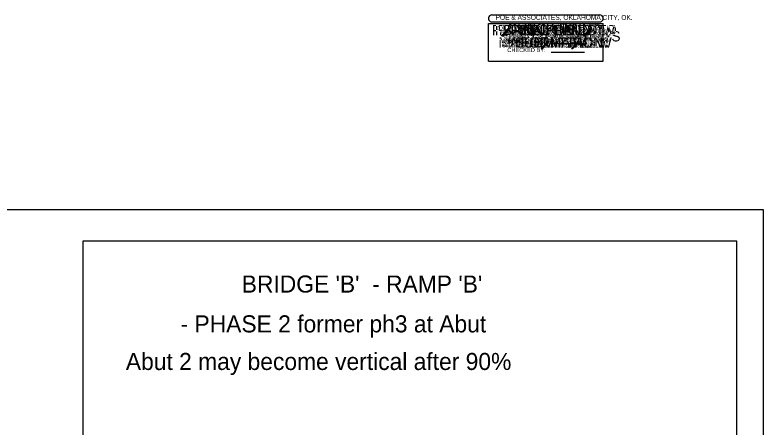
# Model space of a CAD drawing. Extents: x 570 to 2152770, y 726 to 139926.
# Drawn here: x 2152280 to 2152718.5, y 139685 to 139926.4 of the extents above; entities that cross this region are included whole.
import ezdxf

# ---------------------------------------------------------------- set-up
doc = ezdxf.new("R2010")
doc.units = 0
for name, color, linetype in [('S', 7, 'Continuous'), ('SHT_Stamp_30_Submit', 7, 'Continuous'), ('SHT_Stamp_70_Submit', 7, 'Continuous'), ('SHT_Stamp_Check_Print', 7, 'Continuous'), ('SHT_Stamp_Est_Inf', 7, 'Continuous'), ('SHT_Stamp_FFR', 7, 'Continuous'), ('SHT_Stamp_Info_Material', 7, 'Continuous'), ('SHT_Stamp_No_Const', 7, 'Continuous'), ('SHT_Stamp_No_Design', 7, 'Continuous'), ('SHT_Stamp_Plan_Hand', 7, 'Continuous'), ('SHT_Stamp_Pre_Plan', 7, 'Continuous'), ('SHT_Stamp_Prop_RW', 7, 'Continuous'), ('SHT_Stamp_Ret_Sub', 7, 'Continuous'), ('SHT_Stamp_Rev_Prop_RW', 7, 'Continuous'), ('SHT_Stamp_Rev_Sheet', 7, 'Continuous'), ('SHT_Stamp_RW_Utilities_Meeting', 7, 'Continuous'), ('SHT_Stamp_RW_Utilities_Review', 7, 'Continuous'), ('SHT_Stamp_Send_Comments', 7, 'Continuous')]:
    doc.layers.add(name, color=color, linetype=linetype)

msp = doc.modelspace()

# ---------------------------------------------------------------- linework, layer by layer
at = {"layer": 'S'}
for points in [[(2151790.38, 139812.49), (2152718.5, 139812.49), (2152718.5, 139247.24), (2151790.38, 139247.24)], [(2152319.83, 139266.32), (2152703.21, 139266.32), (2152703.21, 139793.9), (2152319.83, 139793.9)]]:
    msp.add_lwpolyline(points, close=True, dxfattribs=at)
at = {"layer": 'SHT_Stamp_30_Submit'}
for p, q in [((2152559.53, 139926.42), (2152622.84, 139926.42)), ((2152557.53, 139921.42), (2152624.84, 139921.42)), ((2152557.53, 139899.43), (2152557.53, 139921.42)), ((2152559.53, 139922.42), (2152622.84, 139922.42)), ((2152624.84, 139899.43), (2152624.84, 139921.42)), ((2152582.39, 139914.65), (2152585.5, 139918.1)), ((2152582.75, 139914.65), (2152585.86, 139918.1)), ((2152582.85, 139914.65), (2152585.96, 139918.1)), ((2152583, 139914.65), (2152586.11, 139918.1)), ((2152585.5, 139918.1), (2152586.11, 139918.1)), ((2152582.39, 139914.65), (2152583, 139914.65)), ((2152557.53, 139899.43), (2152624.84, 139899.43))]:
    msp.add_line(p, q, dxfattribs=at)
for centre, start, end in [((2152559.53, 139924.42), 89.9952, 270), ((2152622.85, 139924.42), 270, 90.0048)]:
    msp.add_arc(centre, 2, start, end, dxfattribs=at)
at = {"layer": 'SHT_Stamp_70_Submit'}
for p, q in [((2152559.53, 139926.42), (2152622.84, 139926.42)), ((2152557.53, 139921.42), (2152624.84, 139921.42)), ((2152557.53, 139899.43), (2152557.53, 139921.42)), ((2152559.53, 139922.42), (2152622.84, 139922.42)), ((2152624.84, 139899.43), (2152624.84, 139921.42)), ((2152582.39, 139914.65), (2152585.5, 139918.1)), ((2152582.75, 139914.65), (2152585.86, 139918.1)), ((2152582.85, 139914.65), (2152585.96, 139918.1)), ((2152583, 139914.65), (2152586.11, 139918.1)), ((2152585.5, 139918.1), (2152586.11, 139918.1)), ((2152582.39, 139914.65), (2152583, 139914.65)), ((2152557.53, 139899.43), (2152624.84, 139899.43))]:
    msp.add_line(p, q, dxfattribs=at)
for centre, start, end in [((2152559.53, 139924.42), 89.9952, 270), ((2152622.85, 139924.42), 270, 90.0048)]:
    msp.add_arc(centre, 2, start, end, dxfattribs=at)
at = {"layer": 'SHT_Stamp_Check_Print'}
for p, q in [((2152559.53, 139926.42), (2152622.84, 139926.42)), ((2152557.53, 139921.42), (2152624.84, 139921.42)), ((2152557.53, 139899.43), (2152557.53, 139921.42)), ((2152559.53, 139922.42), (2152622.84, 139922.42)), ((2152624.84, 139899.43), (2152624.84, 139921.42)), ((2152594.36, 139909.79), (2152613.77, 139909.79)), ((2152594.36, 139904.68), (2152613.77, 139904.68)), ((2152557.53, 139899.43), (2152624.84, 139899.43))]:
    msp.add_line(p, q, dxfattribs=at)
for centre, start, end in [((2152559.53, 139924.42), 89.9952, 270), ((2152622.85, 139924.42), 270, 90.0048)]:
    msp.add_arc(centre, 2, start, end, dxfattribs=at)
at = {"layer": 'SHT_Stamp_Est_Inf'}
for p, q in [((2152559.53, 139926.42), (2152622.84, 139926.42)), ((2152557.53, 139921.42), (2152624.84, 139921.42)), ((2152557.53, 139899.43), (2152557.53, 139921.42)), ((2152559.53, 139922.42), (2152622.84, 139922.42)), ((2152624.84, 139899.43), (2152624.84, 139921.42)), ((2152557.53, 139899.43), (2152624.84, 139899.43))]:
    msp.add_line(p, q, dxfattribs=at)
for centre, start, end in [((2152559.53, 139924.42), 89.9952, 270), ((2152622.85, 139924.42), 270, 90.0048)]:
    msp.add_arc(centre, 2, start, end, dxfattribs=at)
at = {"layer": 'SHT_Stamp_FFR'}
for p, q in [((2152559.53, 139926.42), (2152622.84, 139926.42)), ((2152557.53, 139921.42), (2152624.84, 139921.42)), ((2152557.53, 139899.43), (2152557.53, 139921.42)), ((2152559.53, 139922.42), (2152622.84, 139922.42)), ((2152624.84, 139899.43), (2152624.84, 139921.42)), ((2152557.53, 139899.43), (2152624.84, 139899.43))]:
    msp.add_line(p, q, dxfattribs=at)
for centre, start, end in [((2152559.53, 139924.42), 89.9952, 270), ((2152622.85, 139924.42), 270, 90.0048)]:
    msp.add_arc(centre, 2, start, end, dxfattribs=at)
at = {"layer": 'SHT_Stamp_Info_Material'}
for p, q in [((2152559.53, 139926.42), (2152622.84, 139926.42)), ((2152557.53, 139921.42), (2152624.84, 139921.42)), ((2152557.53, 139899.43), (2152557.53, 139921.42)), ((2152559.53, 139922.42), (2152622.84, 139922.42)), ((2152624.84, 139899.43), (2152624.84, 139921.42)), ((2152557.53, 139899.43), (2152624.84, 139899.43))]:
    msp.add_line(p, q, dxfattribs=at)
for centre, start, end in [((2152559.53, 139924.42), 89.9952, 270), ((2152622.85, 139924.42), 270, 90.0048)]:
    msp.add_arc(centre, 2, start, end, dxfattribs=at)
at = {"layer": 'SHT_Stamp_No_Const'}
for p, q in [((2152559.53, 139926.42), (2152622.84, 139926.42)), ((2152557.53, 139921.42), (2152624.84, 139921.42)), ((2152557.53, 139899.43), (2152557.53, 139921.42)), ((2152559.53, 139922.42), (2152622.84, 139922.42)), ((2152624.84, 139899.43), (2152624.84, 139921.42)), ((2152557.53, 139899.43), (2152624.84, 139899.43))]:
    msp.add_line(p, q, dxfattribs=at)
for centre, start, end in [((2152559.53, 139924.42), 89.9952, 270), ((2152622.85, 139924.42), 270, 90.0048)]:
    msp.add_arc(centre, 2, start, end, dxfattribs=at)
at = {"layer": 'SHT_Stamp_No_Design'}
for p, q in [((2152559.53, 139926.42), (2152622.84, 139926.42)), ((2152557.53, 139921.42), (2152624.84, 139921.42)), ((2152557.53, 139899.43), (2152557.53, 139921.42)), ((2152559.53, 139922.42), (2152622.84, 139922.42)), ((2152624.84, 139899.43), (2152624.84, 139921.42)), ((2152557.53, 139899.43), (2152624.84, 139899.43))]:
    msp.add_line(p, q, dxfattribs=at)
for centre, start, end in [((2152559.53, 139924.42), 89.9952, 270), ((2152622.85, 139924.42), 270, 90.0048)]:
    msp.add_arc(centre, 2, start, end, dxfattribs=at)
at = {"layer": 'SHT_Stamp_Plan_Hand'}
for p, q in [((2152559.53, 139926.42), (2152622.84, 139926.42)), ((2152557.53, 139921.42), (2152624.84, 139921.42)), ((2152557.53, 139899.43), (2152557.53, 139921.42)), ((2152559.53, 139922.42), (2152622.84, 139922.42)), ((2152624.84, 139899.43), (2152624.84, 139921.42)), ((2152557.53, 139899.43), (2152624.84, 139899.43))]:
    msp.add_line(p, q, dxfattribs=at)
for centre, start, end in [((2152559.53, 139924.42), 89.9952, 270), ((2152622.85, 139924.42), 270, 90.0048)]:
    msp.add_arc(centre, 2, start, end, dxfattribs=at)
at = {"layer": 'SHT_Stamp_Pre_Plan'}
for p, q in [((2152559.53, 139926.42), (2152622.84, 139926.42)), ((2152557.53, 139921.42), (2152624.84, 139921.42)), ((2152557.53, 139899.43), (2152557.53, 139921.42)), ((2152559.53, 139922.42), (2152622.84, 139922.42)), ((2152624.84, 139899.43), (2152624.84, 139921.42)), ((2152557.53, 139899.43), (2152624.84, 139899.43))]:
    msp.add_line(p, q, dxfattribs=at)
for centre, start, end in [((2152559.53, 139924.42), 89.9952, 270), ((2152622.85, 139924.42), 270, 90.0048)]:
    msp.add_arc(centre, 2, start, end, dxfattribs=at)
at = {"layer": 'SHT_Stamp_Prop_RW'}
for p, q in [((2152559.53, 139926.42), (2152622.84, 139926.42)), ((2152557.53, 139921.42), (2152624.84, 139921.42)), ((2152557.53, 139899.43), (2152557.53, 139921.42)), ((2152559.53, 139922.42), (2152622.84, 139922.42)), ((2152624.84, 139899.43), (2152624.84, 139921.42)), ((2152588.46, 139906.87), (2152592.3, 139911.13)), ((2152588.9, 139906.87), (2152592.74, 139911.13)), ((2152589.02, 139906.87), (2152592.86, 139911.13)), ((2152589.22, 139906.87), (2152593.06, 139911.13)), ((2152592.3, 139911.13), (2152593.06, 139911.13)), ((2152588.46, 139906.87), (2152589.22, 139906.87)), ((2152557.53, 139899.43), (2152624.84, 139899.43))]:
    msp.add_line(p, q, dxfattribs=at)
for centre, start, end in [((2152559.53, 139924.42), 89.9952, 270), ((2152622.85, 139924.42), 270, 90.0048)]:
    msp.add_arc(centre, 2, start, end, dxfattribs=at)
at = {"layer": 'SHT_Stamp_Ret_Sub'}
for p, q in [((2152559.53, 139926.42), (2152622.84, 139926.42)), ((2152557.53, 139921.42), (2152624.84, 139921.42)), ((2152557.53, 139899.43), (2152557.53, 139921.42)), ((2152559.53, 139922.42), (2152622.84, 139922.42)), ((2152624.84, 139899.43), (2152624.84, 139921.42)), ((2152557.53, 139899.43), (2152624.84, 139899.43))]:
    msp.add_line(p, q, dxfattribs=at)
for centre, start, end in [((2152559.53, 139924.42), 89.9952, 270), ((2152622.85, 139924.42), 270, 90.0048)]:
    msp.add_arc(centre, 2, start, end, dxfattribs=at)
at = {"layer": 'SHT_Stamp_Rev_Prop_RW'}
for p, q in [((2152559.53, 139926.42), (2152622.84, 139926.42)), ((2152557.53, 139921.42), (2152624.84, 139921.42)), ((2152557.53, 139899.43), (2152557.53, 139921.42)), ((2152559.53, 139922.42), (2152622.84, 139922.42)), ((2152624.84, 139899.43), (2152624.84, 139921.42)), ((2152606.26, 139906.81), (2152610.1, 139911.07)), ((2152606.7, 139906.81), (2152610.54, 139911.07)), ((2152606.83, 139906.81), (2152610.67, 139911.07)), ((2152607.02, 139906.81), (2152610.86, 139911.07)), ((2152610.1, 139911.07), (2152610.86, 139911.07)), ((2152606.26, 139906.81), (2152607.02, 139906.81)), ((2152557.53, 139899.43), (2152624.84, 139899.43))]:
    msp.add_line(p, q, dxfattribs=at)
for centre, start, end in [((2152559.53, 139924.42), 89.9952, 270), ((2152622.85, 139924.42), 270, 90.0048)]:
    msp.add_arc(centre, 2, start, end, dxfattribs=at)
at = {"layer": 'SHT_Stamp_Rev_Sheet'}
for p, q in [((2152559.53, 139926.42), (2152622.84, 139926.42)), ((2152557.53, 139921.42), (2152624.84, 139921.42)), ((2152557.53, 139899.43), (2152557.53, 139921.42)), ((2152559.53, 139922.42), (2152622.84, 139922.42)), ((2152624.84, 139899.43), (2152624.84, 139921.42)), ((2152557.53, 139899.43), (2152624.84, 139899.43))]:
    msp.add_line(p, q, dxfattribs=at)
for centre, start, end in [((2152559.53, 139924.42), 89.9952, 270), ((2152622.85, 139924.42), 270, 90.0048)]:
    msp.add_arc(centre, 2, start, end, dxfattribs=at)
at = {"layer": 'SHT_Stamp_RW_Utilities_Meeting'}
for p, q in [((2152559.53, 139926.42), (2152622.84, 139926.42)), ((2152557.53, 139921.42), (2152624.84, 139921.42)), ((2152557.53, 139899.43), (2152557.53, 139921.42)), ((2152559.53, 139922.42), (2152622.84, 139922.42)), ((2152624.84, 139899.43), (2152624.84, 139921.42)), ((2152565.56, 139914.21), (2152569.4, 139918.47)), ((2152566, 139914.21), (2152569.84, 139918.47)), ((2152566.13, 139914.21), (2152569.97, 139918.47)), ((2152566.32, 139914.21), (2152570.16, 139918.47)), ((2152569.4, 139918.47), (2152570.16, 139918.47)), ((2152565.56, 139914.21), (2152566.32, 139914.21)), ((2152557.53, 139899.43), (2152624.84, 139899.43))]:
    msp.add_line(p, q, dxfattribs=at)
for centre, start, end in [((2152559.53, 139924.42), 89.9952, 270), ((2152622.85, 139924.42), 270, 90.0048)]:
    msp.add_arc(centre, 2, start, end, dxfattribs=at)
at = {"layer": 'SHT_Stamp_RW_Utilities_Review'}
for p, q in [((2152559.53, 139926.42), (2152622.84, 139926.42)), ((2152557.53, 139921.42), (2152624.84, 139921.42)), ((2152557.53, 139899.43), (2152557.53, 139921.42)), ((2152559.53, 139922.42), (2152622.84, 139922.42)), ((2152624.84, 139899.43), (2152624.84, 139921.42)), ((2152613.34, 139914.21), (2152617.18, 139918.47)), ((2152613.78, 139914.21), (2152617.62, 139918.47)), ((2152613.9, 139914.21), (2152617.74, 139918.47)), ((2152614.1, 139914.21), (2152617.94, 139918.47)), ((2152617.18, 139918.47), (2152617.94, 139918.47)), ((2152613.34, 139914.21), (2152614.1, 139914.21)), ((2152557.53, 139899.43), (2152624.84, 139899.43))]:
    msp.add_line(p, q, dxfattribs=at)
for centre, start, end in [((2152559.53, 139924.42), 89.9952, 270), ((2152622.85, 139924.42), 270, 90.0048)]:
    msp.add_arc(centre, 2, start, end, dxfattribs=at)
at = {"layer": 'SHT_Stamp_Send_Comments'}
for p, q in [((2152559.53, 139926.42), (2152622.84, 139926.42)), ((2152557.53, 139921.42), (2152624.84, 139921.42)), ((2152557.53, 139899.43), (2152557.53, 139921.42)), ((2152559.53, 139922.42), (2152622.84, 139922.42)), ((2152624.84, 139899.43), (2152624.84, 139921.42)), ((2152557.53, 139899.43), (2152624.84, 139899.43))]:
    msp.add_line(p, q, dxfattribs=at)
for centre, start, end in [((2152559.53, 139924.42), 89.9952, 270), ((2152622.85, 139924.42), 270, 90.0048)]:
    msp.add_arc(centre, 2, start, end, dxfattribs=at)

# ---------------------------------------------------------------- texts
at = {"layer": 'S'}
for s, p in [("BRIDGE 'B'  - RAMP 'B' ", (2152412.96, 139763.78)), ('- PHASE 2 former ph3 at Abut', (2152377.1, 139740.45)), ('Abut 2 may become vertical after 90%', (2152345.03, 139718.42))]:
    msp.add_text(s, height=10, dxfattribs=at).set_placement(p)
at = {"layer": 'SHT_Stamp_30_Submit'}
for s, height, p in [('POE & ASSOCIATES, OKLAHOMA CITY, OK.', 2.8, (2152561.73, 139923.56)), ('30   PLAN', 6, (2152575.57, 139914.58)), ('O', 3.06, (2152581.7, 139916.35)), ('O', 3.06, (2152584.74, 139914.66)), ('SUBMITTAL', 6, (2152572.95, 139907.24))]:
    msp.add_text(s, height=height, dxfattribs=at).set_placement(p)
at = {"layer": 'SHT_Stamp_70_Submit'}
for s, height, p in [('POE & ASSOCIATES, OKLAHOMA CITY, OK.', 2.8, (2152561.73, 139923.56)), ('70   PLAN', 6, (2152575.43, 139914.58)), ('O', 3.06, (2152581.7, 139916.35)), ('O', 3.06, (2152584.74, 139914.66)), ('SUBMITTAL', 6, (2152572.95, 139907.24))]:
    msp.add_text(s, height=height, dxfattribs=at).set_placement(p)
at = {"layer": 'SHT_Stamp_Check_Print'}
for s, height, p in [('POE & ASSOCIATES, OKLAHOMA CITY, OK.', 2.8, (2152561.73, 139923.57)), ('CHECK PRINT', 6, (2152568.58, 139915.44)), ('REVISED BY:', 2.4, (2152568.6, 139909.78)), ('CHECKED BY:', 2.4, (2152568.6, 139904.68))]:
    msp.add_text(s, height=height, dxfattribs=at).set_placement(p)
at = {"layer": 'SHT_Stamp_Est_Inf'}
for s, height, p in [('POE & ASSOCIATES, OKLAHOMA CITY, OK.', 2.8, (2152561.73, 139923.57)), ('BASED ON EST.', 6, (2152566.15, 139914.58)), ('INFORMATION', 6, (2152568.58, 139907.24))]:
    msp.add_text(s, height=height, dxfattribs=at).set_placement(p)
at = {"layer": 'SHT_Stamp_FFR'}
for s, height, p in [('POE & ASSOCIATES, OKLAHOMA CITY, OK.', 2.8, (2152561.73, 139923.57)), ('FINAL FIELD', 6, (2152570.56, 139914.58)), ('REVIEW', 6, (2152579.11, 139907.24))]:
    msp.add_text(s, height=height, dxfattribs=at).set_placement(p)
at = {"layer": 'SHT_Stamp_Info_Material'}
for s, height, p in [('POE & ASSOCIATES, OKLAHOMA CITY, OK.', 2.8, (2152561.73, 139923.57)), ('INFORMATION', 6, (2152568.58, 139914.58)), ('MATERIAL ONLY', 6, (2152563.41, 139907.24))]:
    msp.add_text(s, height=height, dxfattribs=at).set_placement(p)
at = {"layer": 'SHT_Stamp_No_Const'}
for s, height, p in [('POE & ASSOCIATES, OKLAHOMA CITY, OK.', 2.8, (2152561.73, 139923.57)), ('NOT TO BE USED', 6, (2152562.34, 139914.58)), ('FOR CONST.', 6, (2152572.15, 139907.24))]:
    msp.add_text(s, height=height, dxfattribs=at).set_placement(p)
at = {"layer": 'SHT_Stamp_No_Design'}
for s, height, p in [('POE & ASSOCIATES, OKLAHOMA CITY, OK.', 2.8, (2152561.73, 139923.57)), ('NOT TO BE USED', 6, (2152562.34, 139914.58)), ('FOR DESIGN', 6, (2152571.79, 139907.24))]:
    msp.add_text(s, height=height, dxfattribs=at).set_placement(p)
at = {"layer": 'SHT_Stamp_Plan_Hand'}
for s, height, p in [('POE & ASSOCIATES, OKLAHOMA CITY, OK.', 2.8, (2152561.73, 139923.57)), ('PLAN-IN-HAND', 6, (2152567.21, 139910.91))]:
    msp.add_text(s, height=height, dxfattribs=at).set_placement(p)
at = {"layer": 'SHT_Stamp_Pre_Plan'}
for s, height, p in [('POE & ASSOCIATES, OKLAHOMA CITY, OK.', 2.8, (2152561.73, 139923.57)), ('PRELIMINARY', 6, (2152568.89, 139914.58)), ('PLANS', 6, (2152581.03, 139907.24))]:
    msp.add_text(s, height=height, dxfattribs=at).set_placement(p)
at = {"layer": 'SHT_Stamp_Prop_RW'}
for s, height, p in [('POE & ASSOCIATES, OKLAHOMA CITY, OK.', 2.8, (2152561.73, 139923.57)), ('PROPOSED', 6, (2152575.71, 139914.58)), ('R W', 6, (2152584.36, 139907.24))]:
    msp.add_text(s, height=height, dxfattribs=at).set_placement(p)
at = {"layer": 'SHT_Stamp_Ret_Sub'}
for s, height, p in [('POE & ASSOCIATES, OKLAHOMA CITY, OK.', 2.8, (2152561.73, 139923.57)), ('RET. SUBMITTED', 6, (2152565.89, 139914.58)), ('MATERIALS', 6, (2152572.71, 139907.24))]:
    msp.add_text(s, height=height, dxfattribs=at).set_placement(p)
at = {"layer": 'SHT_Stamp_Rev_Prop_RW'}
for s, height, p in [('POE & ASSOCIATES, OKLAHOMA CITY, OK.', 2.8, (2152561.73, 139923.57)), ('REVISED', 6, (2152578.26, 139914.58)), ('PROPOSED R W', 6, (2152566.55, 139907.24))]:
    msp.add_text(s, height=height, dxfattribs=at).set_placement(p)
at = {"layer": 'SHT_Stamp_Rev_Sheet'}
for s, height, p in [('POE & ASSOCIATES, OKLAHOMA CITY, OK.', 2.8, (2152561.73, 139923.57)), ('REVISED SHEET', 6, (2152566.22, 139910.91))]:
    msp.add_text(s, height=height, dxfattribs=at).set_placement(p)
at = {"layer": 'SHT_Stamp_RW_Utilities_Meeting'}
for s, height, p in [('POE & ASSOCIATES, OKLAHOMA CITY, OK.', 2.8, (2152561.73, 139923.56)), ('R W & UTILITIES', 6, (2152561.42, 139914.58)), ('MEETING', 6, (2152576.8, 139907.24))]:
    msp.add_text(s, height=height, dxfattribs=at).set_placement(p)
at = {"layer": 'SHT_Stamp_RW_Utilities_Review'}
for s, height, p in [('POE & ASSOCIATES, OKLAHOMA CITY, OK.', 2.8, (2152561.73, 139923.56)), ('PRELIMINARY R W', 6, (2152559.51, 139914.58)), ('& UTIL.  REVIEW', 6, (2152565.18, 139907.24))]:
    msp.add_text(s, height=height, dxfattribs=at).set_placement(p)
at = {"layer": 'SHT_Stamp_Send_Comments'}
for s, height, p in [('POE & ASSOCIATES, OKLAHOMA CITY, OK.', 2.8, (2152561.73, 139923.57)), ('SEND COMMENTS', 6, (2152563.64, 139910.91))]:
    msp.add_text(s, height=height, dxfattribs=at).set_placement(p)

doc.saveas('drawing.dxf')
